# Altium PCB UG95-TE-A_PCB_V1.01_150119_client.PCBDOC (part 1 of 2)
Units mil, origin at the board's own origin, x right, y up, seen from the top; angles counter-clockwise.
Board outline 1460.63 x 2271.65 mil, 4 copper layers (Top, Inner Layer 2, Inner Layer 3, Bottom), stack 35.4 mil thick; 48 components, 69 nets, 290 pads, 828 vias.
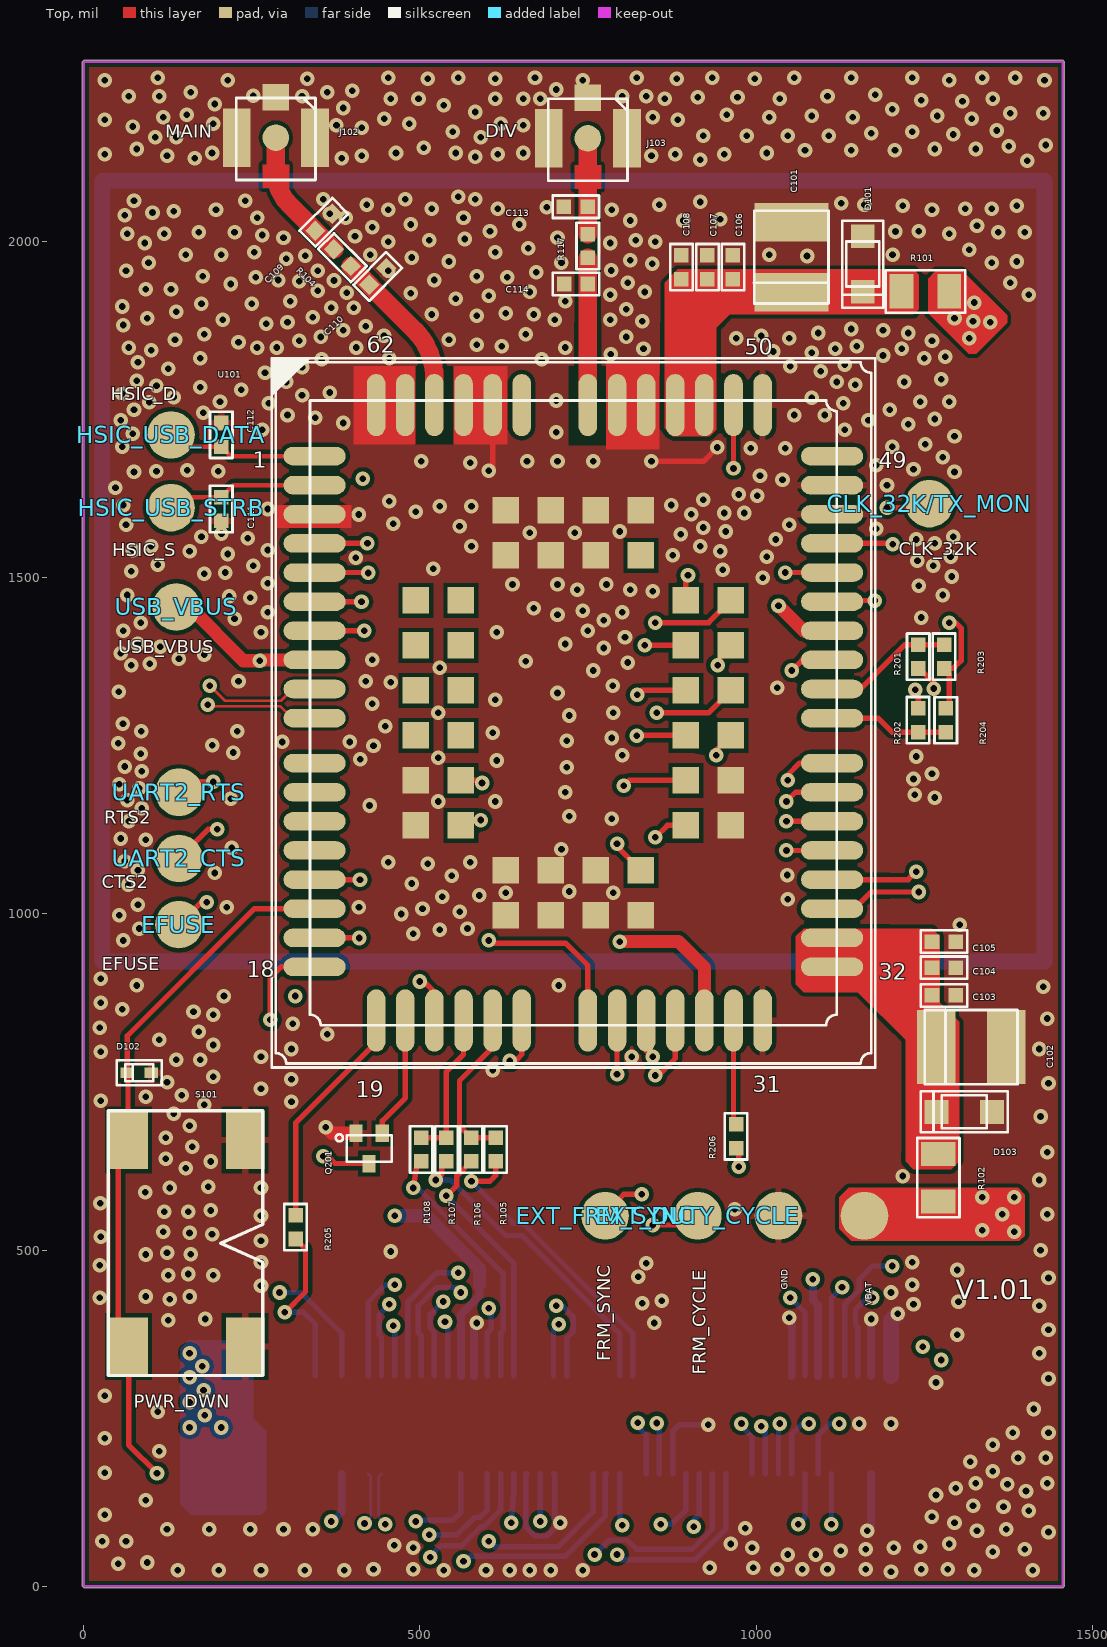
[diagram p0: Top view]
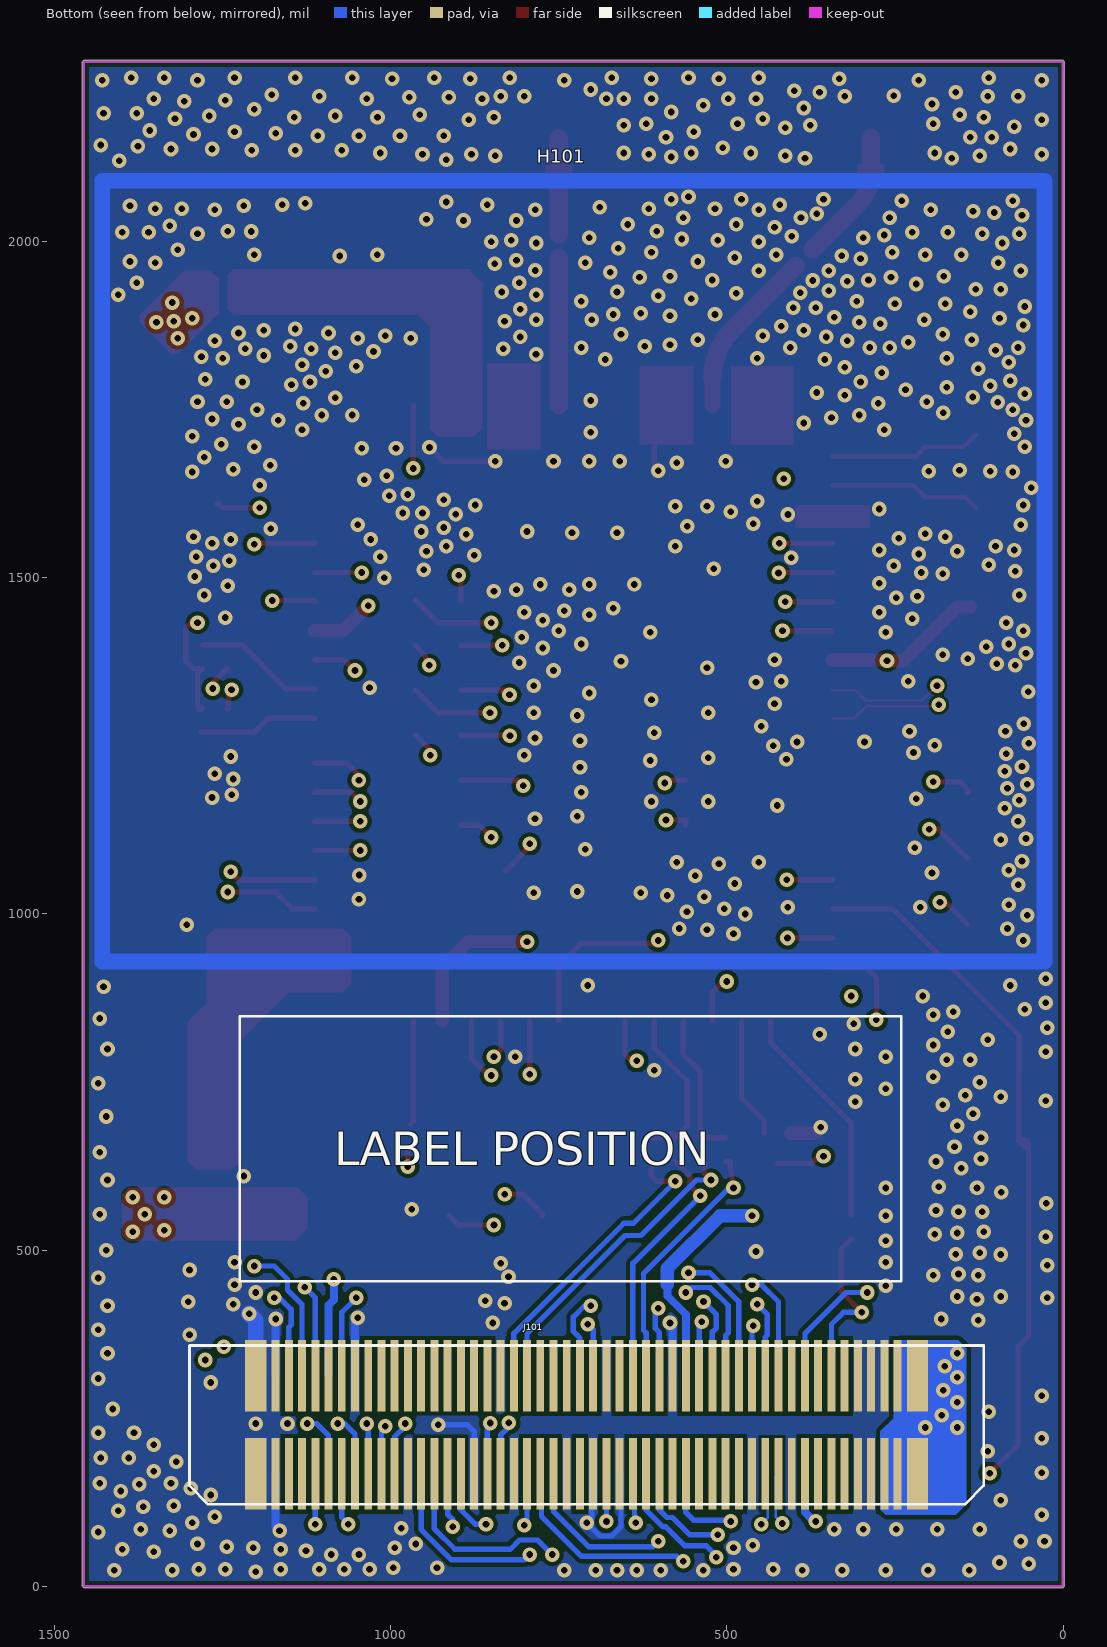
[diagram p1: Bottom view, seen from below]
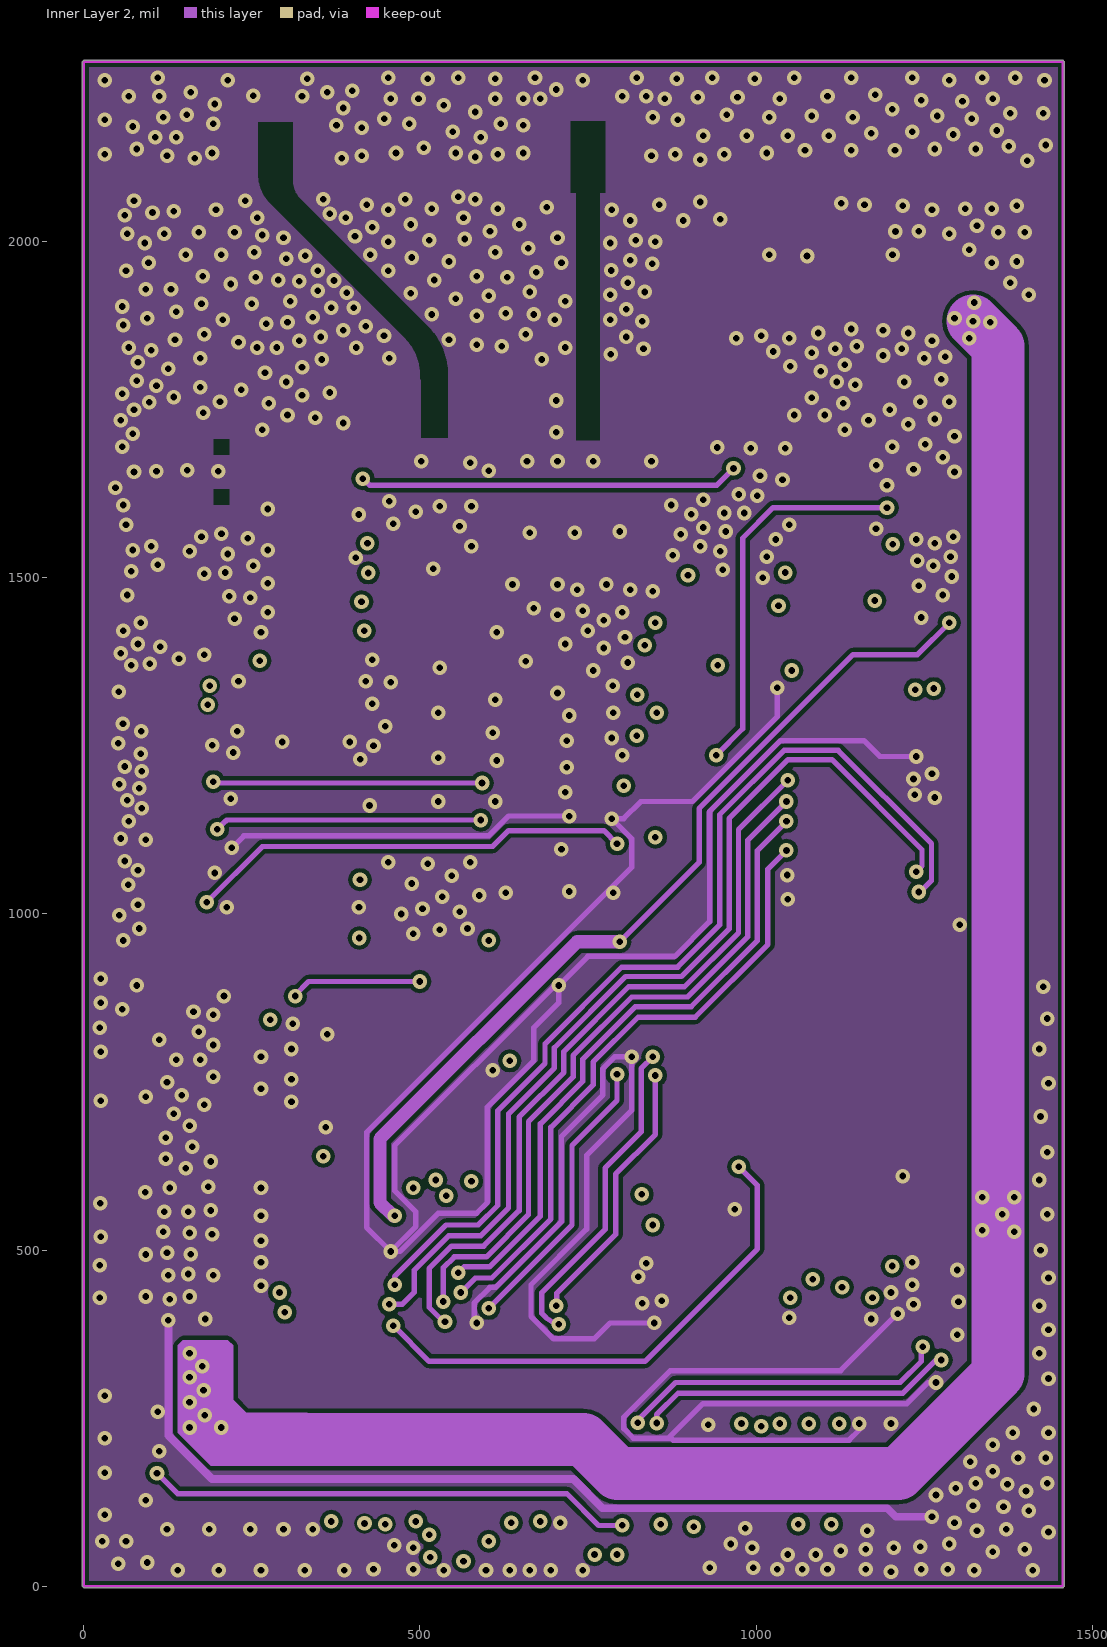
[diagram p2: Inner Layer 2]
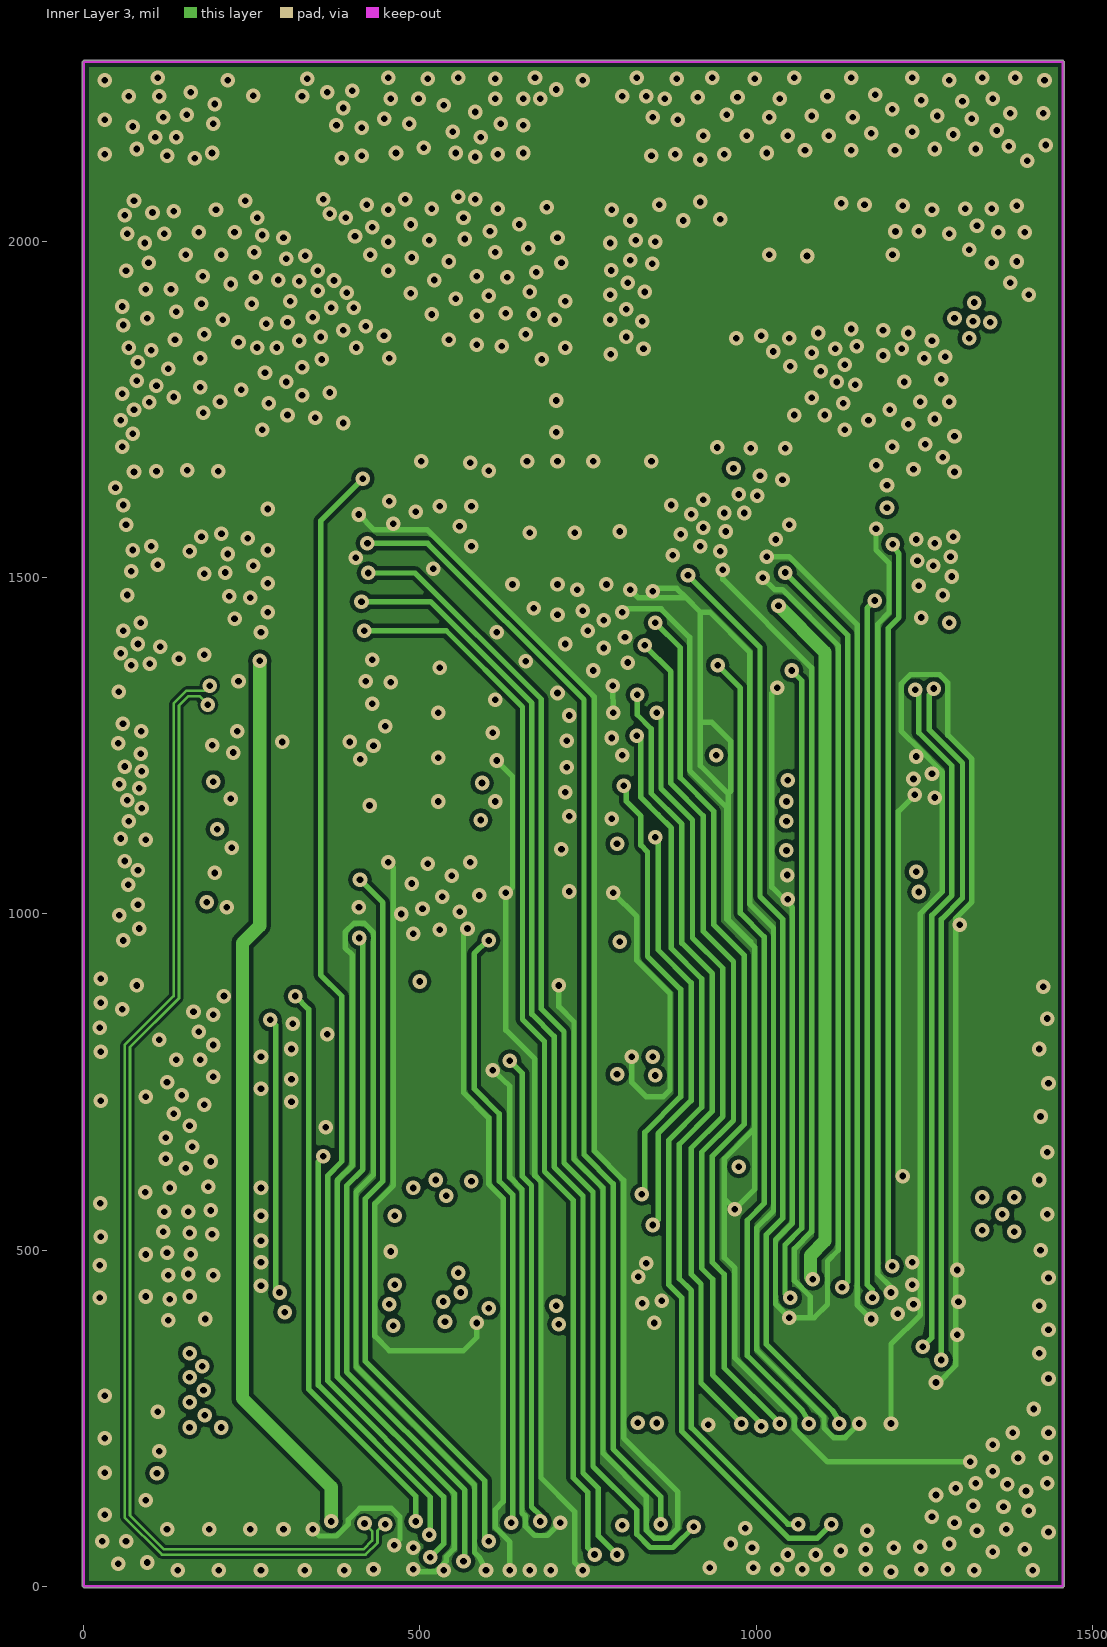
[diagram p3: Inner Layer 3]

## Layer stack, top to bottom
Top: signal copper 1.35
Dielectric: dielectric 10, FR-4, Dk 4.3
Inner Layer 2: signal copper 1.35
Dielectric: dielectric 10, FR-4, Dk 4.3
Inner Layer 3: signal copper 1.35
Dielectric: dielectric 10, FR-4, Dk 4.3
Bottom: signal copper 1.35

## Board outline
-1.97,0 0,-1.97 1456.69,-1.97 1458.66,0 1458.66,2267.72 1456.69,2269.68 0,2269.68 -1.97,2267.72

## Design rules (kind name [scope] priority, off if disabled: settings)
Clearance Poly [InNamedPolygon('GND-I2C_SCL_EVB')] p1: gap=10
Clearance "'Net' PADS rule_31" [InNet('USB-')] p2: gap=3.94
Clearance "'Net' PADS rule_30" [InNet('USB-') And (IsTrack Or IsArc) vs (IsTrack Or IsArc)] p3: gap=3.94
Clearance "'Net' PADS rule_24" [InNet('USB+')] p4: gap=3.94
Clearance "'Net' PADS rule_23" [InNet('USB+') And (IsTrack Or IsArc) vs (IsTrack Or IsArc)] p5: gap=3.94
Clearance "'Default' PADS rule_18" [All] p6: gap=6
Clearance "'Default' PADS rule_15" [IsVia vs IsVia] p7: gap=0
ComponentClearance "'Default' PADS rule_12" [All] p1: gap=0.24 collisioncheckmode=3 verticalgap=10
FlightTimeFalling "'Default' PADS rule_6" [All] p1: maximum=10.00
FlightTimeRising "'Default' PADS rule_5" [All] p1: maximum=10.00
Length "'Default' PADS rule" [All] p1: maxlimit=50000 minlimit=0
MatchedLengths "'Default' PADS rule_7" [InNetClass('All Nets')] p1: tolerance=200 checknetsindiffpair=TRUE checkdiffpairvsdiffpair=TRUE checkothers=TRUE
MaxMinImpedance "'Default' PADS rule_4" [All] p1: minimum=50.00 maximum=150.0
ParallelSegment "'Default' PADS rule_3" [All] p1: limit=1000 gap=200
ParallelSegment "'Default' PADS rule_2" [All] p2: limit=1000 gap=200
PlaneClearance "'Net' PADS rule_35" [InNet('$$$24864')] p1: clearance=7.87
PlaneClearance "'Net' PADS rule_33" [InNet('ANT')] p2: clearance=7.87
PlaneClearance "'Net' PADS rule_29" [InNet('USB-')] p3: clearance=7.87
PlaneClearance "'Net' PADS rule_28" [InNet('HSIC_USB_STRB')] p4: clearance=7.87
PlaneClearance "'Net' PADS rule_26" [InNet('HSIC_USB_DATA')] p5: clearance=7.87
PlaneClearance "'Net' PADS rule_22" [InNet('USB+')] p6: clearance=7.87
PlaneClearance "'Net' PADS rule_21" [InNet('$$$15410')] p7: clearance=7.87
PlaneClearance "'Net' PADS rule_19" [InNet('ANT_DIV')] p8: clearance=7.87
PlaneClearance "'Default' PADS rule_14" [All] p9: clearance=6
PlaneConnect "Power Plane Connect Style - from global settings" [All] p1: planeconnectstyle=Relief reliefexpansion=20 reliefentries=2 reliefconductorwidth=15 reliefairgap=10
PolygonConnect PolygonConnect_1 [IsPad] p1: connectstyle=Relief reliefconductorwidth=10 reliefentries=4 polygonreliefangle="90 Angle"
PolygonConnect LCC [Ispad] p2: connectstyle=Relief reliefconductorwidth=10 reliefentries=4 polygonreliefangle="45 Angle"
PolygonConnect LGA [All] p3: connectstyle=Direct reliefconductorwidth=10 reliefentries=4 polygonreliefangle="90 Angle"
PolygonConnect GND-PAD [Incomponent('gnd')] p4: connectstyle=Relief reliefconductorwidth=10 reliefentries=4 polygonreliefangle="45 Angle"
PolygonConnect GND-Via [IsVia or Ispad] p5: connectstyle=Direct reliefconductorwidth=10 reliefentries=4 polygonreliefangle="90 Angle"
PolygonConnect [All] p6: connectstyle=Relief reliefconductorwidth=10 reliefentries=4 polygonreliefangle="90 Angle"
RoutingLayers "'Default' PADS rule_10" [All] p1: top layer_v5=TRUE mid layer 1_v5=TRUE mid layer 2_v5=TRUE bottom layer_v5=TRUE
RoutingPriority "'Default' PADS rule_9" [All] p1: routingpriority=3
RoutingTopology "'Default' PADS rule_8" [All] p1: topology=Shortest
RoutingVias "'Default' PADS rule_11" [All] p1: holewidth=9.84 width=21.65 viastyle="Through Hole" minholewidth=9.84 minwidth=21.65 maxholewidth=9.84 maxwidth=21.65
SMDToCorner "'Default' PADS rule_16" [All] p1: distance=0
SMDToPlane "'Default' PADS rule_17" [All] p1: distance=40000
SolderMaskExpansion [All] p1: expansion=4
TestPointUsage [All] p1: valid=0 allowmultiple=FALSE
Testpoint [All] p1: side=15 testpointundercomponent=TRUE minsize=40 maxsize=100 preferedsize=60 minholesize=0 maxholesize=40 preferedholesize=32 testpointgrid=1 style=1023 order=0-112345678
Width "'Net' PADS rule_34" [InNet('$$$24864')] p1: maxlimit=196.85 minlimit=3 preferedwidth=27.56
Width "'Net' PADS rule_32" [InNet('ANT')] p2: maxlimit=196.85 minlimit=3 preferedwidth=27.56
Width "'Net' PADS rule_27" [InNet('HSIC_USB_STRB')] p3: maxlimit=196.85 minlimit=3 preferedwidth=6.89
Width "'Net' PADS rule_25" [InNet('HSIC_USB_DATA')] p4: maxlimit=196.85 minlimit=3 preferedwidth=6.89
Width "'Net' PADS rule_20" [InNet('$$$15410')] p5: maxlimit=196.85 minlimit=3 preferedwidth=27.56
Width "'Net' PADS rule" [InNet('ANT_DIV')] p6: maxlimit=196.85 minlimit=3 preferedwidth=27.56
Width "'Default' PADS rule_13" [All] p7: maxlimit=196.85 minlimit=3 preferedwidth=8
13 further rules are at their usual default settings.

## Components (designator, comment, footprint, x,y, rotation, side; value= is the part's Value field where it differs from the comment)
C101 "3528T(B)-M" 3528T(B)-M 1052.68,1976.97 r90 top
C102 "3528T(B)-M" 3528T(B)-M 1320.08,802.05 r0 top
C103 "C-0402" C-0402 1279.53,878.82 r0 top
C104 "C-0402" C-0402 1279.53,920.16 r0 top
C105 "C-0402" C-0402 1279.53,958.94 r0 top
C106 "C-0402" C-0402 965.63,1962.01 r90 top
C107 "C-0402" C-0402 927.76,1962.01 r90 top
C108 "C-0402" C-0402 889.09,1962.01 r90 top
C109 "C-0402" C-0402 357.24,2028.94 r45 top
C110 "C-0402" C-0402 437.28,1948.23 r225 top
C111 "C-0402" C-0402 204.72,1602.36 r270 top
C112 "C-0402" C-0402 204.72,1712.6 r90 top
C113 "C-0402" C-0402 732.09,2051.93 r180 top
C114 "C-0402" C-0402 732.28,1937.01 r0 top
CLK_32K/TX_MON "TTPTPA1R8" TTPTPA1R8 1257.87,1610.24 r0 top
D101 "SOD-323" SOD-323 1158.9,1966.77 r90 top
D102 "SOD-923" SOD-923 82.68,763.78 r0 top
D103 "SOD-323" SOD-323 1309.88,705.71 r0 top
EFUSE "TTPTPA1R8" TTPTPA1R8 141.73,984.25 r180 top
EXT_DUTY_CYCLE "TTPTPA1R8" TTPTPA1R8 913.39,551.18 r0 top
EXT_FRM_SYNC "TTPTPA1R8" TTPTPA1R8 775.59,551.18 r0 top
GND "TTPTPA1R8" TTPTPA1R8 1033.46,551.18 r0 top
HSIC_USB_DATA "TTPTPA1R8" TTPTPA1R8 129.92,1712.6 r0 top
HSIC_USB_STRB "TTPTPA1R8" TTPTPA1R8 129.92,1604.33 r0 top
J101 "AXK600347YG" AXK600347YG 708.66,240.16 r0 bottom
J102 "UFL-R-SMT-1" UFL-R-SMT-1 285.84,2154.73 r0 top
J103 "UFL-R-SMT-1" UFL-R-SMT-1 749.84,2153.7 r0 top
Q201 "EMT3" EMT3 424.57,651.3 r180 top
R101 "R-0805" R-0805 1251.97,1925.98 r180 top
R102 "R-0805" R-0805 1271.22,607.8 r90 top
R104 "R-0402" R-0402 384.84,1976.26 r315 top
R105 "R-0402" R-0402 612.72,649.65 r270 top
R106 "R-0402" R-0402 576.5,649.65 r270 top
R107 "R-0402" R-0402 539.49,649.65 r270 top
R108 "R-0402" R-0402 502.01,649.65 r270 top
R117 "R-0402" R-0402 749.8,1993.62 r270 top
R201 "R-0402" R-0402 1241.24,1382.83 r270 top
R202 "R-0402" R-0402 1241.06,1288.29 r90 top
R203 "R-0402" R-0402 1279.82,1382.83 r270 top
R204 "R-0402" R-0402 1282.15,1288.15 r90 top
R205 "R-0402" R-0402 315.28,534.28 r270 top
R206 "R-0402" R-0402 970.47,669.29 r270 top
S101 "SMT_KEY4N" SMT_KEY4N 216.54,510.35 r270 top
U101 "UG96" UG96 728.35,1299.21 r0 top
UART2_CTS "TTPTPA1R8" TTPTPA1R8 141.73,1082.68 r0 top
UART2_RTS "TTPTPA1R8" TTPTPA1R8 141.73,1181.1 r0 top
USB_VBUS "TTPTPA1R8" TTPTPA1R8 137.8,1456.69 r0 top
VBAT "TTPTPA1R8" TTPTPA1R8 1161.42,551.18 r0 top

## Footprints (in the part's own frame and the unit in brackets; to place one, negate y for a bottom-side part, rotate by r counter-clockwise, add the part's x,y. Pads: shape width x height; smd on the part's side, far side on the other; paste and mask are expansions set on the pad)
3528T(B)-M [mm]
  rect 1.45x2.8 smd mask+0.05: 1(-1.325,0) 2(1.325,0)
  silkscreen extent -1.75,-1.41 1.75,1.42
AXK600347YG [mm]
  rect 0.8x2.7 smd paste-0.2 mask+0.015: 1(12.5,1.85) 2(12.5,-1.85) 99(-12.5,1.85) 100(-12.5,-1.85)
  rect 0.3x2.7 smd paste-0.2 mask+0.015: 3(11.75,1.85) 4(11.75,-1.85) 5(11.25,1.85) 6(11.25,-1.85) 7(10.75,1.85) 8(10.75,-1.85) 9(10.25,1.85) 10(10.25,-1.85) 11(9.75,1.85) 12(9.75,-1.85) 13(9.25,1.85) 14(9.25,-1.85) 15(8.75,1.85) 16(8.75,-1.85) 17(8.25,1.85) 18(8.25,-1.85) 19(7.75,1.85) 20(7.75,-1.85) 21(7.25,1.85) 22(7.25,-1.85) 23(6.75,1.85) 24(6.75,-1.85) 25(6.25,1.85) 26(6.25,-1.85) 27(5.75,1.85) 28(5.75,-1.85) 29(5.25,1.85) 30(5.25,-1.85) 31(4.75,1.85) 32(4.75,-1.85) 33(4.25,1.85) 34(4.25,-1.85) 35(3.75,1.85) 36(3.75,-1.85) 37(3.25,1.85) 38(3.25,-1.85) 39(2.75,1.85) 40(2.75,-1.85) 41(2.25,1.85) 42(2.25,-1.85) 43(1.75,1.85) 44(1.75,-1.85) 45(1.25,1.85) 46(1.25,-1.85) 47(0.75,1.85) 48(0.75,-1.85) 49(0.25,1.85) 50(0.25,-1.85) 51(-0.25,1.85) 52(-0.25,-1.85) 53(-0.75,1.85) 54(-0.75,-1.85) 55(-1.25,1.85) 56(-1.25,-1.85) 57(-1.75,1.85) 58(-1.75,-1.85) 59(-2.25,1.85) 60(-2.25,-1.85) 61(-2.75,1.85) 62(-2.75,-1.85) 63(-3.25,1.85) 64(-3.25,-1.85) 65(-3.75,1.85) 66(-3.75,-1.85) 67(-4.25,1.85) 68(-4.25,-1.85) 69(-4.75,1.85) 70(-4.75,-1.85) 71(-5.25,1.85) 72(-5.25,-1.85) 73(-5.75,1.85) 74(-5.75,-1.85) 75(-6.25,1.85) 76(-6.25,-1.85) 77(-6.75,1.85) 78(-6.75,-1.85) 79(-7.25,1.85) 80(-7.25,-1.85) 81(-7.75,1.85) 82(-7.75,-1.85) 83(-8.25,1.85) 84(-8.25,-1.85) 85(-8.75,1.85) 86(-8.75,-1.85) 87(-9.25,1.85) 88(-9.25,-1.85) 89(-9.75,1.85) 90(-9.75,-1.85) 91(-10.25,1.85) 92(-10.25,-1.85) 93(-10.75,1.85) 94(-10.75,-1.85) 95(-11.25,1.85) 96(-11.25,-1.85) 97(-11.75,1.85) 98(-11.75,-1.85)
  silkscreen extent -15,-3 15,3
C-0402 [mm]
  rect 0.55x0.55 smd mask+0.05: 1(-0.45,0) 2(0.45,0)
  silkscreen extent -0.87,-0.43 0.87,0.43
EMT3 [mm]
  rect 0.5x0.66 smd mask+0.05: 1(0.5,-0.57) 2(-0.5,-0.57) 3(0,0.57)
  silkscreen extent -0.85,-0.53 1.26,0.5
R-0402 [mm]
  rect 0.55x0.55 smd mask+0.05: 1(-0.45,0) 2(0.45,0)
  silkscreen extent -0.88,-0.42 0.88,0.42
R-0805 [mm]
  rect 0.9x1.3 smd mask+0.05: 1(-0.9,0) 2(0.9,0)
  silkscreen extent -1.5,-0.8 1.5,0.8
SMT_KEY4N [mm]
  rect 2.2x1.45 smd mask+0.05: 1(-3.9,0.6) 2(-3.9,-3.8) 3(3.9,-3.8) 4(3.9,0.6)
  silkscreen extent -5,-4.57 5,1.27
SOD-323 [mm]
  rect 0.9x0.9 smd mask+0.05: 1(-1.05,0) 2(1.05,0)
  silkscreen extent -1.65,-0.78 1.64,0.77
SOD-923 [mm]
  rect 0.5x0.4 smd mask+0.05: 1(-0.45,0) 2(0.45,0)
  silkscreen extent -0.85,-0.48 0.85,0.48
TTPTPA1R8 [mm]
  round 1.8 smd mask+0.05: 1(0,0)
UFL-R-SMT-1 [mm]
  round 1 smd: 1(0,0)
  rect 1.05x2.2 smd mask+0.05: 2(1.475,0) 4(-1.475,0)
  rect 1x1 smd mask+0.05: 3(0,1.525)
  Top region: -0.265,-0.05 0.265,-0.05 0.265,-1.523 -0.265,-1.523 -0.265,-0.05
  Top region: -0.499,-1.021 0.501,-1.021 0.501,-1.898 -0.499,-1.898 -0.499,-1.021
  silkscreen extent -1.5,-1.6 1.5,1.51
UG96 [mm]
  oval 2.35x0.7 smd mask+0.05: 1(-9.775,9.7) 2(-9.775,8.6) 3(-9.775,7.5) 4(-9.775,6.4) 5(-9.775,5.3) 6(-9.775,4.2) 7(-9.775,3.1) 8(-9.775,2) 9(-9.775,0.9) 10(-9.775,-0.2) 11(-9.775,-1.9) 12(-9.775,-3) 13(-9.775,-4.1) 14(-9.775,-5.2) 15(-9.775,-6.3) 16(-9.775,-7.4) 17(-9.775,-8.5) 18(-9.775,-9.6) 32(9.775,-9.6) 33(9.775,-8.5) 34(9.775,-7.4) 35(9.775,-6.3) 36(9.775,-5.2) 37(9.775,-4.1) 38(9.775,-3) 39(9.775,-1.9) 40(9.775,-0.2) 41(9.775,0.9) 42(9.775,2) 43(9.775,3.1) 44(9.775,4.2) 45(9.775,5.3) 46(9.775,6.4) 47(9.775,7.5) 48(9.775,8.6) 49(9.775,9.7)
  oval 0.7x2.35 smd mask+0.05: 19(-7.45,-11.625) 20(-6.35,-11.625) 21(-5.25,-11.625) 22(-4.15,-11.625) 23(-3.05,-11.625) 24(-1.95,-11.625) 25(0.55,-11.625) 26(1.65,-11.625) 27(2.75,-11.625) 28(3.85,-11.625) 29(4.95,-11.625) 30(6.05,-11.625) 31(7.15,-11.625) 50(7.15,11.625) 51(6.05,11.625) 52(4.95,11.625) 53(3.85,11.625) 54(2.75,11.625) 55(1.65,11.625) 56(0.55,11.625) 57(-1.95,11.625) 58(-3.05,11.625) 59(-4.15,11.625) 60(-5.25,11.625) 61(-6.35,11.625) 62(-7.45,11.625)
  rect 1x1 smd mask+0.05: 63(-5.95,4.25) 64(-5.95,2.55) 65(-5.95,0.85) 66(-5.95,-0.85) 67(-5.95,-2.55) 68(-5.95,-4.25) 69(-2.55,-7.65) 70(-0.85,-7.65) 71(0.85,-7.65) 72(2.55,-7.65) 73(5.95,-4.25) 74(5.95,-2.55) 75(5.95,-0.85) 76(5.95,0.85) 77(5.95,2.55) 78(5.95,4.25) 79(2.55,7.65) 80(0.85,7.65) 81(-0.85,7.65) 82(-2.55,7.65) 83(-4.25,4.25) 84(-4.25,2.55) 85(-4.25,0.85) 86(-4.25,-0.85) 87(-4.25,-2.55) 88(-4.25,-4.25) 89(-2.55,-5.95) 90(-0.85,-5.95) 91(0.85,-5.95) 92(2.55,-5.95) 93(4.25,-4.25) 94(4.25,-2.55) 95(4.25,-0.85) 96(4.25,0.85) 97(4.25,2.55) 98(4.25,4.25) 99(2.55,5.95) 100(0.85,5.95) 101(-0.85,5.95) 102(-2.55,5.95)
  silkscreen extent -11.4,-13.4 11.4,13.41

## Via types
v1: diameter 21.65, hole 9.84, Top to Bottom, 828 vias

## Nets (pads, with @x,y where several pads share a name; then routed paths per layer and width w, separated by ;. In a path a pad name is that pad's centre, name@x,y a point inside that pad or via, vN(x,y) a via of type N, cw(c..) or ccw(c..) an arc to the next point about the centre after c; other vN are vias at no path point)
$$$15410: C113.1 J103.1 R117.1 | length 142.4
  Top w23.62: J103.1@749.8,2153.66 J103.1@749.84,2153.7
  Top w27.56: R117.1@749.8,2011.34 C113.1@749.8,2051.93 J103.1@749.8,2153.66
$$$24864: C109.1 J102.1 R104.1 | length 198.8
  Top w27.56: J102.1@285.84,2154.73 285.84,2103.66 ccw(c354.36,2103.66) 305.91,2055.22 C109.1@344.72,2016.41 R104.1@372.32,1988.79
ADC: J101.53 U101.24 | length 846.8
  Top w8: v1(633.86,781.5) 635.53,783.17 643.7,783.17 651.57,791.04 U101.24@651.57,841.54
  Inner Layer 3 w8: v1(633.86,781.5) 652.45,762.9 652.45,609.7 666.08,596.07 666.08,118.11 679.13,105.05 v1(679.13,96.46)
  Bottom w8: v1(679.13,96.46) J101.53@679.13,167.32
ANT: C110.2 R104.2 U101.60 | length 253.9
  Top w23.62: C110.2@424.76,1935.7 C110.2@424.76,1936.35 ; U101.60@521.65,1756.89 U101.60@521.65,1796.57
  Top w27.56: R104.2@397.37,1963.73 C110.2@424.76,1936.35 ; C110.2@424.76,1935.7 491.79,1868.66 cw(c419.7,1796.57) U101.60@521.65,1796.57
ANT_DIV: C114.2 R117.2 U101.56 | length 219.1
  Top w23.62: R117.2@749.8,1975.91 R117.2@750,1975.71
  Top w27.56: U101.56@750,1756.89 C114.2@750,1937.01 R117.2@750,1975.71
AP_READY: J101.88 R205.2 | length 257.2
  Top w8: v1(299.21,407.48) 329.88,438.15 329.88,501.96 R205.2@315.28,516.56
  Bottom w8: v1(299.21,407.48) 326.77,407.48 344.49,389.76 J101.88@344.49,312.99
AP_READY/AP_WAKEUP: R205.1 U101.19 | length 339.1
  Top w8: R205.1@315.28,551.99 315.28,689.3 435.04,809.06 U101.19@435.04,841.54
CLK_32K/TX_MONITOR: CLK_32K/TX_MON.1 U101.75 | length 676.4
  Top w8: v1(940.94,1236.22) 940.94,1244.09 U101.75@962.6,1265.75 ; v1(1194.88,1604.33) 1250,1604.33 1255.91,1610.24 CLK_32K/TX_MON.1@1257.87,1610.24
  Inner Layer 2 w8: v1(940.94,1236.22) 980.32,1275.59 980.32,1559.06 1025.59,1604.33 v1(1194.88,1604.33)
CLKOUT: J101.57 U101.25 | length 1218.7
  Top w8: v1(602.36,960.63) 606.3,956.69 716.54,956.69 750,923.23 U101.25@750,841.54
  Inner Layer 3 w8: v1(602.36,960.63) 600.39,960.63 580.71,940.94 580.71,740.16 618.11,702.76 618.11,602.58 638.02,582.68 638.02,96.68 v1(635.83,94.49)
  Bottom w8: v1(635.83,94.49) 639.76,140.39 J101.57@639.76,167.32
CTS: J101.72 U101.36 | length 1173.7
  Top w8: v1(1045.28,1094.49) U101.36@1113.19,1094.49
  Inner Layer 2 w8: v1(561.02,437.01) 582.68,458.66 606.98,458.66 694.88,546.56 694.88,682.68 757.87,745.67 757.87,779.64 824.69,846.46 909.45,846.46 1017.72,954.72 1017.72,1066.93 v1(1045.28,1094.49)
  Bottom w8: J101.72@501.97,312.99 501.97,373.11 498.07,377.01 497.72,377.01 497.72,417.28 524.84,444.41 553.62,444.41 v1(561.02,437.01)
DCD: J101.70 U101.38 | length 1226.3
  Top w8: v1(1045.28,1167.32) 1059.06,1181.1 U101.38@1113.19,1181.1
  Inner Layer 2 w8: v1(534.76,423.58) 534.76,473.67 551.26,490.16 598.88,490.16 661.64,552.91 661.64,691.11 728.13,757.6 728.13,789.49 815.21,876.57 898.28,876.57 987.97,966.26 987.97,1110.02 v1(1045.28,1167.32)
  Bottom w8: J101.70@521.65,312.99 521.65,378.55 515.75,384.46 515.75,404.57 v1(534.76,423.58)
DTR: J101.76 R206.2 | length 881.1
  Top w8: R206.2@970.47,651.57 974.41,647.64 v1(974.41,624.02)
  Inner Layer 2 w8: v1(460.63,387.8) 513.78,334.65 834.65,334.65 1001.97,501.97 1001.97,596.46 v1(974.41,624.02)
  Bottom w8: J101.76@462.6,312.99 v1@462.6,385.83 ; v1@462.6,385.83 v1(460.63,387.8) 462.6,391.65 462.6,387.8 v1@462.6,385.83
DTR/HOST_ACTIVE: R206.1 U101.30 | length 156.2
  Top w8: U101.30@966.54,841.54 966.54,690.94 R206.1@970.47,687.01
EFUSE: EFUSE.1 U101.92 | length 771.7
  Top w8: EFUSE.1@141.73,984.25 175.2,1017.72 v1(183.07,1017.72) ; v1(793.31,1104.33) 793.31,1100.39 U101.92@828.74,1064.96
  Inner Layer 2 w8: v1(183.07,1017.72) 265.75,1100.39 608.27,1100.39 631.89,1124.02 773.62,1124.02 v1(793.31,1104.33)
EXT_DUTY_CYCLE: EXT_DUTY_CYCLE.1 U101.93 | length 753.6
  Top w8: v1(846.46,537.4) 897.64,537.4 898.62,536.42 EXT_DUTY_CYCLE.1@913.39,551.18 ; v1(850.39,1114.17) 868.11,1131.89 U101.93@895.67,1131.89
  Inner Layer 3 w8: v1(846.46,537.4) 854.33,545.28 854.33,673.23 903.54,722.44 903.54,897.64 854.33,946.85 854.33,1114.17 854.33,1116.14 852.36,1116.14 v1(850.39,1114.17)
EXT_FRM_SYNC: EXT_FRM_SYNC.1 U101.94 | length 835.2
  Top w8: EXT_FRM_SYNC.1@775.59,551.18 773.77,553 773.23,553 773.5,553.27 803.3,583.07 v1(830.32,583.07) ; v1(803.15,1190.94) 811.02,1198.82 U101.94@895.67,1198.82
  Inner Layer 3 w8: v1(803.15,1190.94) 807.09,1187.01 807.09,1167.32 828.74,1145.67 828.74,1102.36 838.58,1092.52 838.58,937.01 887.8,887.8 887.8,728.35 834.65,675.2 834.65,587.4 v1(830.32,583.07)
